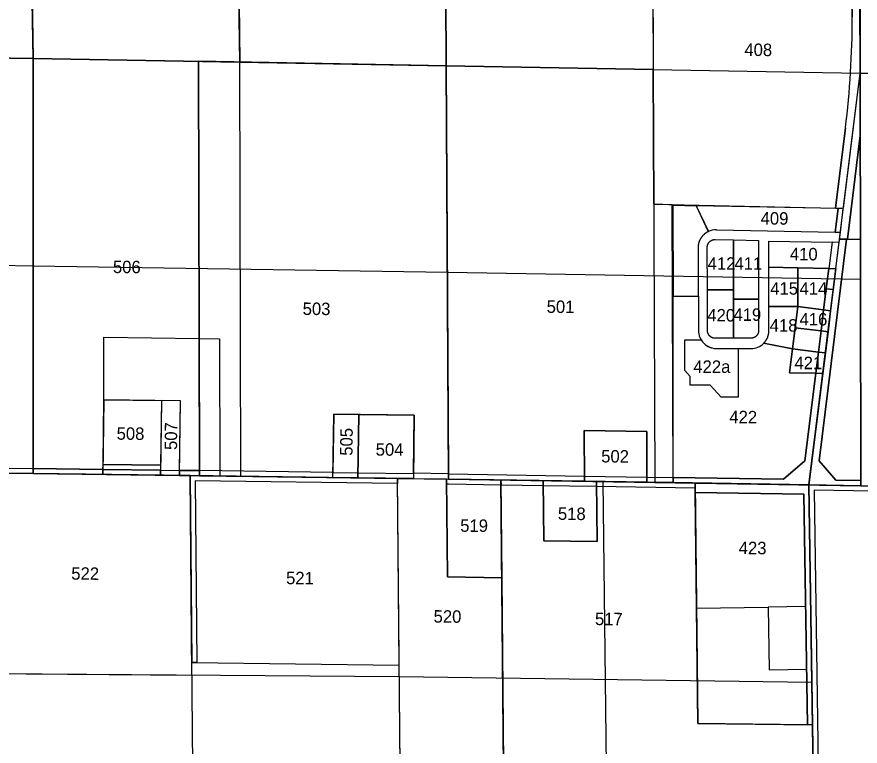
# Model space of a CAD drawing. Extents: x 582596 to 627039, y 145946 to 197316.
# Drawn here: x 599237 to 604634, y 163252 to 167917 of the extents above; entities that cross this region are included whole.
import ezdxf

# ---------------------------------------------------------------- set-up
doc = ezdxf.new("R2010")
doc.units = 0
for name, color, linetype in [('Defpoints 2', 7, 'Continuous'), ('E_RW_Existing', 7, 'Continuous'), ('E_RW_SixteenthLine', 7, 'Continuous'), ('P_MISC_NoPlot', 7, 'Continuous'), ('P_RW_PropertyLine', 7, 'Continuous'), ('P_RW_SectionLine', 7, 'Continuous'), ('P_RW_Text', 7, 'Continuous'), ('Racine_County_Tax_Parcels', 7, 'Continuous')]:
    doc.layers.add(name, color=color, linetype=linetype)

msp = doc.modelspace()

# ---------------------------------------------------------------- linework, layer by layer
at = {"layer": 'Defpoints'}
for p, q in [((604633.8, 167557.8), (604629.4, 170060)), ((604499.3, 166474.7), (604507.4, 166540.2))]:
    msp.add_line(p, q, dxfattribs=at)
for points in [[(604540.4, 167208.9), (604540.4, 167208.9)], [(604489.2, 166659.1), (604489.2, 166659.1)], [(604571.6, 166648.9), (604571.6, 166648.9)], [(604571.6, 166648.7), (604571.6, 166648.7)], [(604449, 166432.8), (604449, 166432.8)], [(604538.3, 166421.7), (604538.3, 166421.7)], [(604538.9, 166426.3), (604538.9, 166426.3)], [(604291.7, 165167.4), (604291.7, 165167.4)], [(604379.9, 165146.9), (604379.9, 165146.9)], [(604381, 165156.3), (604381, 165156.3)]]:
    msp.add_lwpolyline(points, dxfattribs=at)
at = {"layer": 'E_RW_Existing'}
for points in [[(604629.4, 170060), (604633.8, 167557.8)], [(604633.8, 167557.8), (604631.6, 168827.4), (604581.6, 168828.3), (604583.2, 167917.4)], [(604539.9, 167207.1), (604476.1, 166694), (604526.4, 166693), (604633.8, 167557.8)], [(604501.8, 166495.5), (604633.8, 167557.8)], [(604634.5, 167158), (604552.1, 166494.5), (604501.8, 166495.5)], [(604638.5, 164918.1), (604306.5, 164923.5), (604501.8, 166495.5), (604547.1, 166494.6), (604370.9, 165076.3), (604477.4, 164953.7), (604638.4, 164951.1), (604638.5, 164918.1)], [(604461.7, 166172.3), (604417, 166177.8), (604433.2, 166308.3), (604478.5, 166307.5), (604461.7, 166172.3)], [(606975.3, 164845.2), (604340, 164890), (604376.6, 162397.1), (604343.6, 162398.3), (604306.5, 164923.5), (604638.5, 164918.1)]]:
    msp.add_lwpolyline(points, dxfattribs=at)
for points in [[(604474.2, 166540.9), (604507.4, 166540.2), (604526, 166689.9), (604492.8, 166690.6)], [(604499.3, 166474.6), (604454, 166475.6), (604433.2, 166308.3), (604478.5, 166307.5)], [(604417, 166177.8), (604461.7, 166172.3), (604444.9, 166037.6), (604400.3, 166043.1)], [(604400.3, 166043.1), (604444.9, 166037.6), (604428.2, 165902.6), (604383.5, 165908.2)], [(604383.5, 165908.2), (604428.2, 165902.6), (604411.4, 165767.7), (604366.8, 165773.2)], [(604395, 165636.4), (604349.9, 165637.3), (604366.8, 165773.2), (604411.4, 165767.7)], [(604349.9, 165637.4), (604395.1, 165636.7), (604306.5, 164923.5), (603436.7, 164937.7), (603436.7, 164970.7), (604143.8, 164959.2), (604280.4, 165077.8)], [(600156.4, 165050), (600156, 165018), (599788.1, 165022.8), (599788.5, 165054.8)], [(599788.1, 165022.8), (599787.6, 164989.8), (599340.6, 164995.6), (598726.1, 165003.6), (598726.5, 165036.6), (599341.2, 165028.6)], [(600156, 165018), (600155.6, 164985), (599787.6, 164989.8), (599788.1, 165022.8)], [(600278, 165016.4), (600277.6, 164983.4), (600155.6, 164985), (600156, 165018)], [(600406, 165014.8), (600406.1, 164981.8), (600277.6, 164983.4), (600278, 165016.4)], [(601260, 165003.7), (601420, 165001.6), (601419.5, 164968.6), (601259.6, 164970.7)], [(601774.9, 164997), (601774.5, 164964), (601419.5, 164968.6), (601420, 165001.6)], [(601999.5, 164961), (601999.3, 164994.1), (602868.9, 164979.9), (602869, 164946.9)], [(601672.2, 164965.3), (601672.5, 164932.3), (600378.4, 164949.1), (600389.1, 163787.3), (600356.1, 163787.7), (600345.1, 164982.6)], [(602335.1, 164955.6), (602335.4, 164922.6), (601998.9, 164928.1), (601987.5, 164928.2), (601987.2, 164961.2), (601999.5, 164961)], [(602335.4, 164922.6), (602335.1, 164955.6), (602605.7, 164951.2), (602606.1, 164918.2)], [(602945.7, 164945.6), (602946.1, 164912.6), (602606.1, 164918.2), (602605.7, 164951.2)], [(602869, 164946.9), (602868.9, 164979.9), (603268.9, 164973.4), (603269, 164940.4)], [(602869, 164946.9), (602868.9, 164979.9), (603268.9, 164973.4), (603269, 164940.4)], [(602946.1, 164912.6), (602945.7, 164945.6), (603577.5, 164935.4), (603577.8, 164902.4)], [(603268.9, 164973.4), (603436.2, 164970.7), (603436.3, 164937.7), (603269, 164940.4)], [(603268.9, 164973.4), (603436.2, 164970.7), (603436.3, 164937.7), (603269, 164940.4)], [(604329.1, 163388.3), (604296.1, 163388.7), (604274.4, 164864), (603578.2, 164875.3), (603577.5, 164935.4), (604306.5, 164923.5)]]:
    msp.add_lwpolyline(points, close=True, dxfattribs=at)
msp.add_arc((598903.6, 167907.4), 5679.6, 352.9174, 0.1015, dxfattribs=at)
at = {"layer": 'E_RW_SixteenthLine'}
for p, q in [((600663.2, 167628.3), (600633.2, 170287.6)), ((603300, 170253.8), (603309.4, 167581.4)), ((600670, 164978.3), (600663.2, 167628.3)), ((603309.4, 167581.4), (603319, 164939.6)), ((599341, 166323.6), (596687.1, 166359.8)), ((601992.2, 166283), (599341, 166323.6)), ((604636.2, 166238), (601992.2, 166283)), ((600368.6, 162431.3), (600345.1, 164982.6)), ((603019.9, 162413.2), (602989.4, 164944.4)), ((599029.5, 163717.1), (601684.2, 163696.7)), ((601684.2, 163696.7), (604325.1, 163660.9))]:
    msp.add_line(p, q, dxfattribs=at)
at = {"layer": 'P_MISC_NoPlot'}
for points in [[(606993.6, 160308.3), (600102.2, 147849.8), (582596.4, 147849.8), (584141, 197316), (605971.8, 196079.3), (609781.9, 181857.8), (607212.6, 178117.5), (605887.7, 178149.4), (605896.2, 176823.3), (605904.6, 175497.2), (605914.1, 174173.8), (605923.5, 172850.3), (605943, 171523.9), (604673.2, 170334), (604629.1, 170230.1), (604629.4, 170060), (605962, 170045), (605958.9, 168865.5), (605954.8, 167533.5), (604633.8, 167557.8), (604638.5, 164918.1), (606975.2, 164878.2), (606986.2, 162297)], [(606993.6, 160308.3), (600102.2, 147849.8), (582596.4, 147849.8), (584141, 197316), (605971.8, 196079.3), (609781.9, 181857.8), (607212.6, 178117.5), (605887.7, 178149.4), (605896.2, 176823.3), (605904.6, 175497.2), (605914.1, 174173.8), (605923.5, 172850.3), (605943, 171523.9), (604673.2, 170334), (604629.1, 170230.1), (604629.4, 170060), (605962, 170045), (605958.9, 168865.5), (605954.8, 167533.5), (604633.8, 167557.8), (604638.5, 164918.1), (606975.2, 164878.2), (606986.2, 162297)], [(606993.6, 160308.3), (600102.2, 147849.8), (582596.4, 147849.8), (584141, 197316), (605971.8, 196079.3), (609781.9, 181857.8), (607212.6, 178117.5), (605887.7, 178149.4), (605896.2, 176823.3), (605904.6, 175497.2), (605914.1, 174173.8), (605923.5, 172850.3), (605943, 171523.9), (604673.2, 170334), (604629.1, 170230.1), (604629.4, 170060), (605962, 170045), (605958.9, 168865.5), (605954.8, 167533.5), (604633.8, 167557.8), (604638.5, 164918.1), (606975.2, 164878.2), (606986.2, 162297)], [(606996.1, 159645.4), (606986.2, 162297), (606975.2, 164878.2), (604638.5, 164918.1), (604633.8, 167557.8), (605954.8, 167533.5), (605962, 170045), (604629.4, 170060), (604629.1, 170230.1), (604673.2, 170334), (605943, 171523.9), (605923.5, 172850.3), (605914.1, 174173.8), (605904.6, 175497.2), (605896.2, 176823.3), (605887.7, 178149.4), (607212.6, 178117.5), (607212.6, 178117.5), (627039.4, 170600.9), (626501.4, 158385.8), (609890.9, 158385.8), (607772.6, 159126.1)]]:
    msp.add_lwpolyline(points, close=True, dxfattribs=at)
at = {"layer": 'P_RW_PropertyLine'}
for p, q in [((600663.2, 167628.3), (601985, 167604.9)), ((603853.3, 165795.5), (603934.9, 165795.5)), ((600406.1, 164981.8), (600536.4, 164980.1)), ((603587, 164134.3), (604044.8, 164141)), ((604284.8, 164144.6), (604044.8, 164141)), ((604044.8, 164141), (604050.7, 163740.1)), ((604050.7, 163740.1), (604290.6, 163743.6))]:
    msp.add_line(p, q, dxfattribs=at)
for points in [[(599295.6, 170297.8), (599341.4, 167651.7), (598016.8, 167670.6), (597998.5, 168995.3), (599218.6, 168976.3), (599195.6, 170299.4)], [(599341.4, 167651.7), (599299.4, 170077.8), (599399.4, 170077), (599395.6, 170297), (600633.2, 170287.6), (600663.2, 167628.3)], [(601970.8, 170277.5), (603300, 170253.8), (603309.4, 167581.4), (601985, 167604.9)], [(601985, 167604.9), (600663.2, 167628.3), (600648.2, 168958), (601977.9, 168941.2)], [(599341.4, 167651.7), (600399.3, 167633), (600406.1, 164981.8), (600277.6, 164983.4), (600283.8, 165461.4), (599793.8, 165467.8), (599787.6, 164989.8), (599340.6, 164995.6), (598726.1, 165003.6), (598732.3, 165481.6), (598242.3, 165487.9), (598236.1, 165010), (598011.2, 165012.9), (598016.8, 167670.6)], [(599341.4, 167651.7), (599340.6, 164995.6), (598726.1, 165003.6), (598732.3, 165481.6), (598242.3, 165487.9), (598236.1, 165010), (598011.2, 165012.9), (598016.8, 167670.6)], [(599341.4, 167651.7), (600399.3, 167633), (600406.1, 164981.8), (600277.6, 164983.4), (600283.8, 165461.4), (599793.8, 165467.8), (599787.6, 164989.8), (599340.6, 164995.6)], [(599340.6, 165028.6), (599341.4, 167651.7), (600399.3, 167633), (600406, 165014.8), (600278, 165016.4), (600283.8, 165461.4), (599793.8, 165467.8), (599788.1, 165022.8)], [(601999.5, 164961), (601985, 167604.9), (600399.3, 167633), (600406.1, 164981.8), (601259.6, 164970.7), (601264.8, 165375.6), (601779.8, 165368.9), (601774.5, 164964)], [(601999.3, 164994.1), (601775, 164997.7), (601779.8, 165368.9), (601264.8, 165375.6), (601260, 165003.7), (600406, 165014.8), (600399.3, 167633), (601985, 167604.9)], [(604400.3, 166043.1), (604234.6, 166063.7), (604235.9, 166311.9), (604433.2, 166308.3), (604417, 166178.1)], [(604383.5, 165908.2), (604217.8, 165928.8), (604234.6, 166063.7), (604400.3, 166043.1)], [(604383.5, 165908.2), (604366.8, 165773.2), (604201, 165793.8), (604217.8, 165928.8)], [(599793.8, 165467.8), (599792.8, 165867.8), (600403.8, 165859.8), (600406.1, 164981.8), (600277.6, 164983.4), (600283.8, 165461.4)], [(600403.8, 165859.8), (600534.2, 165858.1), (600536.3, 164980.1), (600406.1, 164981.8)], [(604349.9, 165637.3), (604181.9, 165639.9), (604201, 165793.8), (604366.8, 165773.2)], [(599788.5, 165054.8), (599793.8, 165467.8), (600161.8, 165463), (600156.4, 165050)], [(601419.5, 164968.6), (601259.6, 164970.7), (601264.8, 165375.6), (601424.8, 165373.6)], [(602869, 164946.9), (603269, 164940.4), (603267.8, 165265.4), (602867.9, 165271.9)], [(599017.9, 164999.8), (599029.5, 163717.1), (600356.9, 163706.9), (600345.1, 164982.6), (599340.6, 164995.6)], [(601672.2, 164965.3), (600345.1, 164982.6), (600356.1, 163787.7), (601683.5, 163770.4)], [(602358, 162420.7), (601696.1, 162428.1), (601672.2, 164965.3), (601987.2, 164961.2), (601993.1, 164335.2), (602341, 164329.6)], [(601999.5, 164961), (602335.1, 164955.6), (602341, 164329.6), (601993.1, 164335.2), (601987.2, 164961.2)], [(604329.1, 163388.3), (604343.6, 162398.3), (604356, 161411.6), (603030.8, 161426.7), (603029.4, 161550), (602366.9, 161557.5), (602358, 162420.7), (602335.1, 164955.6), (602605.7, 164951.2), (602610.3, 164566.2), (602950.3, 164560.7), (602945.7, 164945.6), (603577.5, 164935.4), (603595.8, 163396.6)], [(602605.7, 164951.2), (602945.7, 164945.6), (602950.3, 164560.7), (602610.3, 164566.2)], [(604274.4, 164864), (604296.1, 163388.7), (603595.8, 163396.6), (603578.2, 164875.3)]]:
    msp.add_lwpolyline(points, close=True, dxfattribs=at)
for points in [[(604581.6, 168828.3), (603304.9, 168851.1), (603309.4, 167581.4), (603312.5, 166718.2), (604476.1, 166694), (604539.9, 167207.1)], [(604583.2, 167917.4), (604581.6, 168828.3)], [(601999.5, 164961), (602869, 164946.9), (602867.9, 165271.9), (603267.8, 165265.4), (603269, 164940.4), (603436.3, 164937.7), (603429.9, 166715.8), (603312.5, 166718.2), (603309.4, 167581.4), (601985, 167604.9), (601999.5, 164961)], [(604635.7, 166493), (604552.1, 166494.5), (604634.5, 167158), (604635.7, 166493)], [(603714.4, 166555.3), (604474.2, 166540.9), (604492.8, 166690.6), (603584.2, 166707.8), (603662.2, 166544.1)], [(604454, 166475.6), (604433.2, 166308.3), (604234.2, 166311.9), (604049.2, 166315.4), (604049, 166483.3), (604454, 166475.6)], [(604638.4, 164951.1), (604477.4, 164953.7), (604370.9, 165076.3), (604547.1, 166494.6), (604635.7, 166493)], [(603436.5, 166130.9), (603598.9, 166130.9), (603599, 165911.5)], [(604017.3, 165829.9), (604201, 165793.8), (604181.9, 165639.9), (604349.9, 165637.3), (604280.4, 165077.8), (604143.8, 164959.2), (603436.7, 164970.7), (603436.5, 166130.9)], [(603715, 165795.5), (603934.9, 165795.5)], [(600155.6, 164985), (600277.6, 164983.4), (600283.8, 165461.4), (600161.8, 165463), (600155.6, 164985)], [(601774.5, 164964), (601672.2, 164965.3), (601419.5, 164968.6), (601424.8, 165373.6), (601779.8, 165368.9), (601774.5, 164964)], [(604638.5, 164918.1), (604306.5, 164923.5), (604343.6, 162398.3), (606986.1, 162299.1)]]:
    msp.add_lwpolyline(points, dxfattribs=at)
for centre, radius, start, end in [((598917.1, 167906.5), 5666.1, 352.9089, 0.11), ((603712.1, 166439.4), 116, 88.9051, 115.4853), ((603715, 165911.5), 116, 180.0093, 270.0101), ((603934.9, 165911.5), 116, 270.0103, 315.2496)]:
    msp.add_arc(centre, radius, start, end, dxfattribs=at)
at = {"layer": 'P_RW_SectionLine'}
for p, q in [((599295.6, 170297.8), (599341.4, 167651.7)), ((601970.8, 170277.5), (601985, 167604.9)), ((604633.8, 167557.8), (604629.4, 170060)), ((596692.3, 167689.6), (599341.4, 167651.7)), ((599341.4, 167651.7), (599340.6, 164995.6)), ((599341.4, 167651.7), (601985, 167604.9)), ((601985, 167604.9), (604633.8, 167557.8)), ((601985, 167604.9), (601999.5, 164961)), ((604633.8, 167557.8), (604638.5, 164918.1)), ((604633.8, 167557.8), (605954.8, 167533.5)), ((596681.8, 165030.1), (599340.6, 164995.6)), ((599340.6, 164995.6), (601999.5, 164961)), ((601696.1, 162428.1), (601672.2, 164965.3)), ((601999.5, 164961), (604638.5, 164918.1)), ((604343.6, 162398.3), (604306.5, 164923.5))]:
    msp.add_line(p, q, dxfattribs=at)
at = {"layer": 'P_RW_Text'}
for points in [[(603853.3, 165795.5), (603853.1, 165485.5), (603743.6, 165485.5), (603674.3, 165561), (603546.6, 165561), (603546.7, 165617.2), (603511.7, 165655.2), (603511.8, 165850.3), (603616.4, 165850.4)], [(603715, 165795.5), (603853.3, 165795.5)]]:
    msp.add_lwpolyline(points, dxfattribs=at)
msp.add_arc((603715, 165911.5), 116, 211.8027, 270.0101, dxfattribs=at)
at = {"layer": 'Racine_County_Tax_Parcels'}
for points in [[(603662.9, 166544.4), (603662.6, 166544.2), (603660.2, 166543.1), (603658, 166541.9), (603655.7, 166540.7), (603653.5, 166539.4), (603651.3, 166538.1), (603649.1, 166536.7), (603646.9, 166535.3), (603644.8, 166533.8), (603642.7, 166532.3), (603640.7, 166530.7), (603638.7, 166529.1), (603636.7, 166527.4), (603634.8, 166525.7), (603632.9, 166524), (603631, 166522.2), (603629.2, 166520.4), (603627.4, 166518.5), (603625.7, 166516.6), (603624, 166514.7), (603622.4, 166512.7), (603620.7, 166510.7), (603619.2, 166508.7), (603617.7, 166506.6), (603616.2, 166504.5), (603614.8, 166502.3), (603613.4, 166500.1), (603612.1, 166497.9), (603610.8, 166495.7), (603609.6, 166493.4), (603608.4, 166491.1), (603607.3, 166488.8), (603606.2, 166486.5), (603605.2, 166484.1), (603604.2, 166481.7), (603603.3, 166479.3), (603602.5, 166476.9), (603601.7, 166474.5), (603600.9, 166472), (603600.2, 166469.5), (603599.6, 166467), (603599, 166464.5), (603598.5, 166462), (603598, 166459.5), (603597.6, 166456.9), (603597.2, 166454.4), (603596.9, 166451.8), (603596.7, 166449.3), (603596.5, 166446.7), (603596.3, 166444.1), (603596.3, 166441.5), (603596.2, 166439), (603597.3, 166129.5), (603439.5, 166128.9), (603437.4, 166712), (603584.8, 166708.5)], [(603823.8, 166170.5), (603656, 166170.6), (603655, 166442.7), (603655.1, 166443.8), (603655.1, 166444.9), (603655.1, 166446), (603655.2, 166447.1), (603655.3, 166448.2), (603655.5, 166449.3), (603655.6, 166450.4), (603655.8, 166451.5), (603656, 166452.6), (603656.2, 166453.7), (603656.5, 166454.8), (603656.8, 166455.8), (603657.1, 166456.9), (603657.4, 166458), (603657.7, 166459), (603658.1, 166460.1), (603658.5, 166461.1), (603658.9, 166462.1), (603659.4, 166463.2), (603659.8, 166464.2), (603660.3, 166465.2), (603660.8, 166466.2), (603661.3, 166467.1), (603661.9, 166468.1), (603662.5, 166469), (603663, 166470), (603663.7, 166470.9), (603664.3, 166471.8), (603664.9, 166472.7), (603665.6, 166473.6), (603666.3, 166474.5), (603667, 166475.3), (603667.7, 166476.2), (603668.5, 166477), (603669.3, 166477.8), (603670, 166478.6), (603670.8, 166479.3), (603671.7, 166480.1), (603672.5, 166480.8), (603673.3, 166481.5), (603674.2, 166482.2), (603675.1, 166482.9), (603676, 166483.6), (603676.9, 166484.2), (603677.8, 166484.8), (603678.8, 166485.4), (603679.7, 166486), (603680.7, 166486.5), (603681.7, 166487.1), (603682.6, 166487.6), (603683.6, 166488), (603684.6, 166488.5), (603685.7, 166489), (603686.7, 166489.4), (603687.7, 166489.8), (603688.8, 166490.1), (603689.8, 166490.5), (603690.9, 166490.8), (603692, 166491.1), (603693, 166491.4), (603694.1, 166491.7), (603695.2, 166491.9), (603696.3, 166492.1), (603697.4, 166492.3), (603698.5, 166492.4), (603699.6, 166492.6), (603700.7, 166492.7), (603701.8, 166492.8), (603702.9, 166492.8), (603704, 166492.9), (603705.1, 166492.9), (603706.2, 166492.8), (603823.8, 166490.1)], [(603983.8, 166111.3), (603823.8, 166111.1), (603823.8, 166170.5), (603823.8, 166490.1), (603983.4, 166486.3)], [(604234.7, 166200.9), (604234.9, 166063.9), (604049.9, 166063.6), (604049.6, 166315.6), (604234.5, 166312)], [(603823.8, 166111.1), (603824.1, 165861.1), (603707, 165861), (603705.9, 165861), (603704.8, 165861), (603703.8, 165861.1), (603702.7, 165861.1), (603701.6, 165861.2), (603700.5, 165861.4), (603699.4, 165861.5), (603698.4, 165861.7), (603697.3, 165861.9), (603696.2, 165862.1), (603695.2, 165862.4), (603694.1, 165862.6), (603693.1, 165862.9), (603692, 165863.2), (603691, 165863.6), (603689.9, 165863.9), (603688.9, 165864.3), (603687.9, 165864.7), (603686.9, 165865.2), (603685.9, 165865.6), (603684.9, 165866.1), (603684, 165866.6), (603683, 165867.1), (603682.1, 165867.6), (603681.1, 165868.2), (603680.2, 165868.7), (603679.3, 165869.3), (603678.4, 165869.9), (603677.5, 165870.6), (603676.6, 165871.2), (603675.8, 165871.9), (603674.9, 165872.6), (603674.1, 165873.3), (603673.3, 165874), (603672.5, 165874.8), (603671.7, 165875.5), (603670.9, 165876.3), (603670.2, 165877.1), (603669.5, 165877.9), (603668.7, 165878.7), (603668, 165879.6), (603667.4, 165880.4), (603666.7, 165881.3), (603666.1, 165882.2), (603665.5, 165883.1), (603664.9, 165884), (603664.3, 165884.9), (603663.7, 165885.8), (603663.2, 165886.8), (603662.7, 165887.7), (603662.2, 165888.7), (603661.7, 165889.7), (603661.3, 165890.7), (603660.8, 165891.7), (603660.4, 165892.7), (603660, 165893.7), (603659.7, 165894.7), (603659.3, 165895.8), (603659, 165896.8), (603658.7, 165897.9), (603658.4, 165898.9), (603658.2, 165900), (603658, 165901), (603657.8, 165902.1), (603657.6, 165903.2), (603657.4, 165904.3), (603657.3, 165905.3), (603657.2, 165906.4), (603657.1, 165907.5), (603657, 165908.6), (603657, 165909.7), (603657, 165910.8), (603656, 166170.6), (603823.8, 166170.5)], [(603984, 165911.3), (603984, 165910.2), (603984, 165909.1), (603983.9, 165908), (603983.9, 165906.9), (603983.7, 165905.8), (603983.6, 165904.8), (603983.5, 165903.7), (603983.3, 165902.6), (603983.1, 165901.5), (603982.9, 165900.5), (603982.6, 165899.4), (603982.4, 165898.3), (603982.1, 165897.3), (603981.7, 165896.2), (603981.4, 165895.2), (603981, 165894.2), (603980.7, 165893.2), (603980.3, 165892.1), (603979.8, 165891.1), (603979.4, 165890.1), (603978.9, 165889.2), (603978.4, 165888.2), (603977.9, 165887.2), (603977.4, 165886.3), (603976.8, 165885.3), (603976.2, 165884.4), (603975.6, 165883.5), (603975, 165882.6), (603974.4, 165881.7), (603973.7, 165880.8), (603973.1, 165880), (603972.4, 165879.1), (603971.7, 165878.3), (603970.9, 165877.5), (603970.2, 165876.7), (603969.4, 165875.9), (603968.7, 165875.1), (603967.9, 165874.4), (603967, 165873.7), (603966.2, 165873), (603965.4, 165872.3), (603964.5, 165871.6), (603963.7, 165870.9), (603962.8, 165870.3), (603961.9, 165869.7), (603961, 165869.1), (603960, 165868.5), (603959.1, 165868), (603958.1, 165867.4), (603957.2, 165866.9), (603956.2, 165866.4), (603955.2, 165865.9), (603954.2, 165865.5), (603953.2, 165865.1), (603952.2, 165864.6), (603951.2, 165864.3), (603950.2, 165863.9), (603949.1, 165863.6), (603948.1, 165863.2), (603947, 165862.9), (603946, 165862.7), (603944.9, 165862.4), (603943.8, 165862.2), (603942.8, 165862), (603941.7, 165861.8), (603940.6, 165861.7), (603939.5, 165861.5), (603938.5, 165861.4), (603937.4, 165861.3), (603936.3, 165861.3), (603935.2, 165861.2), (603934.1, 165861.2), (603824.1, 165861.1), (603823.8, 166111.1), (603983.8, 166111.3)], [(604218.1, 165928.9), (604201.3, 165793.9), (604016.2, 165829.3), (604019.7, 165833), (604021.3, 165834.8), (604023, 165836.8), (604024.6, 165838.7), (604026.2, 165840.7), (604027.7, 165842.7), (604029.1, 165844.8), (604030.6, 165846.9), (604031.9, 165849), (604033.3, 165851.2), (604034.6, 165853.3), (604035.8, 165855.5), (604037, 165857.8), (604038.1, 165860), (604039.2, 165862.3), (604040.3, 165864.6), (604041.3, 165867), (604042.2, 165869.3), (604043.1, 165871.7), (604043.9, 165874.1), (604044.7, 165876.5), (604045.4, 165878.9), (604046.1, 165881.3), (604046.7, 165883.8), (604047.3, 165886.2), (604047.8, 165888.7), (604048.3, 165891.2), (604048.7, 165893.7), (604049.1, 165896.2), (604049.4, 165898.7), (604049.6, 165901.2), (604049.8, 165903.8), (604049.9, 165906.3), (604050, 165908.8), (604050, 165911.4), (604049.9, 166063.6), (604234.9, 166063.9)]]:
    msp.add_lwpolyline(points, close=True, dxfattribs=at)

# ---------------------------------------------------------------- texts
at = {"layer": 'Defpoints 2'}
for s, rotation, p in [('408', 359.5042, (603892.8, 167667.9)), ('409', 359.5042, (603996.7, 166589.2)), ('410', 359.5042, (604183.9, 166360.9)), ('506', 359.5042, (599851.5, 166278.7)), ('503', 359.5042, (601065.8, 166010.8)), ('501', 359.5042, (602627.4, 166023.9)), ('420', 359.5065, (603655.4, 165969.7)), ('422', 359.5065, (603796.5, 165318.4)), ('507', 89.5042, (600262.2, 165146.4)), ('508', 359.5042, (599875, 165212.5)), ('505', 89.5042, (601385.1, 165109.6)), ('504', 359.5042, (601533.2, 165110.7)), ('502', 359.5042, (602976.3, 165067.2)), ('518', 359.5065, (602699.3, 164699.8)), ('519', 359.5065, (602074, 164623.7)), ('423', 359.5065, (603856.6, 164480.8)), ('522', 359.5065, (599584.9, 164317.3)), ('521', 359.5065, (600959.6, 164288.3)), ('520', 359.5065, (601903.7, 164042.6)), ('517', 359.5065, (602936.6, 164026.6))]:
    msp.add_text(s, height=79.68, rotation=rotation, dxfattribs=at).set_placement(p)
for s, p in [('412', (603658, 166299.7)), ('411', (603829.5, 166299.7)), ('415', (604058.8, 166140.2)), ('414', (604246.1, 166140.2)), ('419', (603822.9, 165972.8)), ('416', (604246, 165943.3)), ('418', (604055.1, 165903.9)), ('421', (604213.2, 165663.7)), ('422a', (603566.3, 165640.1))]:
    msp.add_text(s, height=79.68, dxfattribs=at).set_placement(p)

doc.saveas('drawing.dxf')
